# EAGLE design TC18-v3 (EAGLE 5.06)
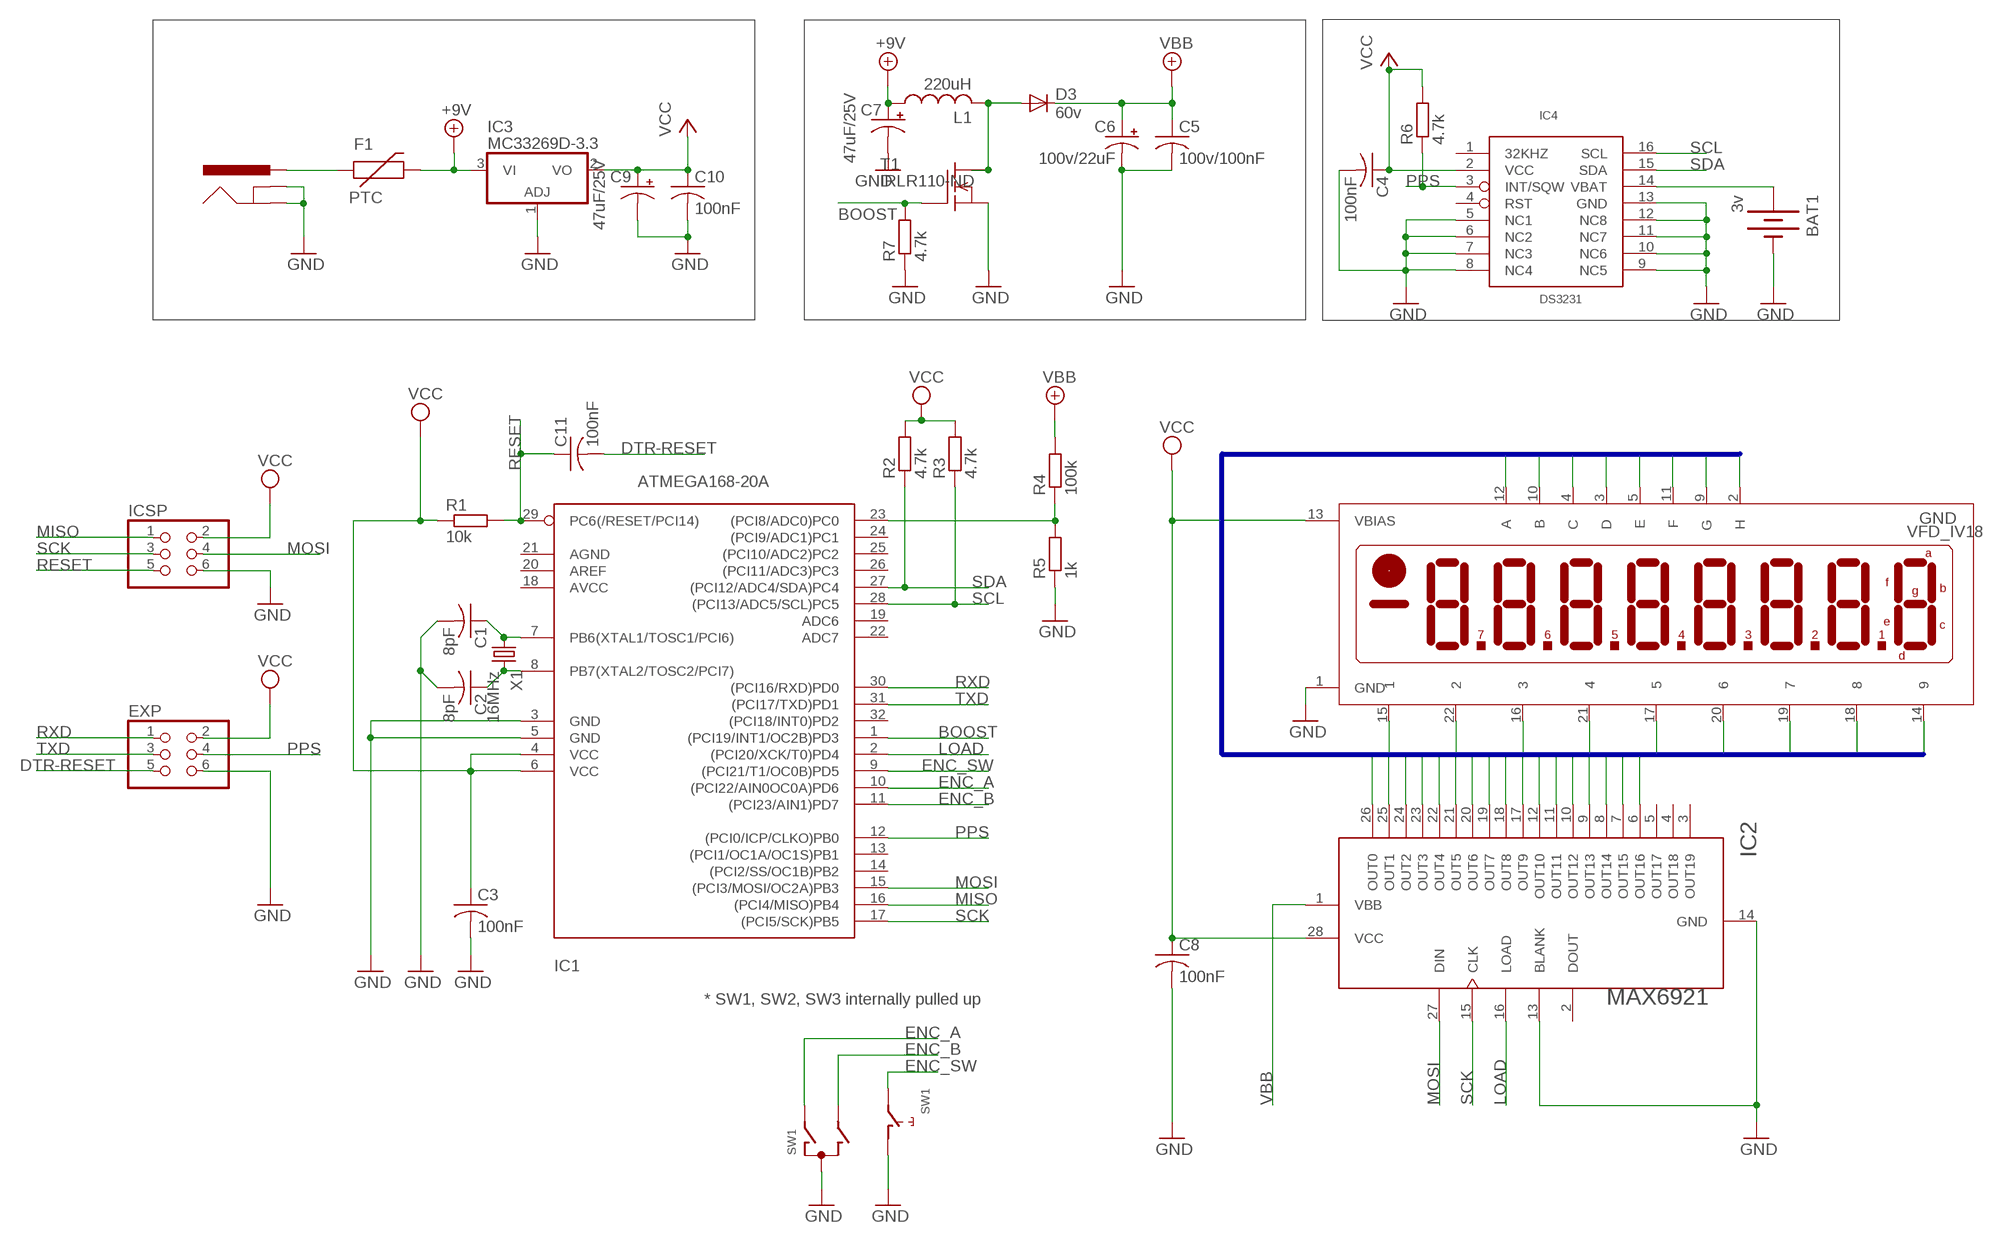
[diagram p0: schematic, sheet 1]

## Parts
BAT1  3v  BATTERY12MM  [BATTCON_12MM]
C1  8pF  C-USC0805  [C0805]
C2  8pF  C-USC0805  [C0805]
C3  100nF  C-USC0805  [C0805]
C4  100nF  C-USC0805  [C0805]
C5  100v/100nF  C-USC0805  [C0805]
C6  100v/22uF  CPOL-USE  [PANASONIC_E]
C7  47uF/25V  CPOL-USD  [PANASONIC_D]
C8  100nF  C-USC0805  [C0805]
C9  47uF/25V  CPOL-USD  [PANASONIC_D]
C10  100nF  C-USC0805  [C0805]
C11  100nF  C-USC0805  [C0805]
D3  60v  DIODE-DO214AA  [DO214AA]
EXP  PINHD-2X3  [2X03]
F1  PTC  [PTC-1210L]
GND  VFD_IV18  [VFD_IV18]
IC1  ATMEGA168-20A  [TQFP32-08]
IC2  MAX6921  MAX6921SOIC28W  [SO-28W]
IC3  MC33269D-3.3  [DPACK]
IC4  DS3231  [SO16W]
ICSP  PINHD-2X3  [2X03]
J1  POWER_JACKSMD  [POWER_JACK_SMD]
L1  220uH  INDUCTOR  [MURATA_4600]
R1  10k  R-EU_R0805  [R0805]
R2  4.7k  R-EU_R0805  [R0805]
R3  4.7k  R-EU_R0805  [R0805]
R4  100k  R-EU_R0805  [R0805]
R5  1k  R-EU_R0805  [R0805]
R6  4.7k  R-EU_R0805  [R0805]
R7  4.7k  R-EU_R0805  [R0805]
SW1  ROT_ENCODER_SW  [ACZ11BRXE-ROTARY-ENCODER-W-SWITCH]
T1  IRLR110-ND  [TO252]
X1  16MHz  CRYSTAL  [CRYSTAL-SMD-5X3.2-2PIN]

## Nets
1: GND.15 IC2.26(OUT0)
2: GND.22 IC2.25(OUT1)
3: GND.16 IC2.24(OUT2)
4: GND.21 IC2.23(OUT3)
5: GND.17 IC2.22(OUT4)
6: GND.20 IC2.21(OUT5)
7: GND.19 IC2.20(OUT6)
8: GND.18 IC2.19(OUT7)
9: GND.14 IC2.18(OUT8)
+9V [Power]: C7.+ F1.P$2 IC3.3(VI) L1.P$1
A: GND.12(A) IC2.17(OUT9)
B: GND.10(B) IC2.12(OUT10)
BOOST: IC1.1((PCI19/INT1/OC2B)PD3) R7.2 T1.1(G)
C: GND.4(C) IC2.11(OUT11)
D: GND.3(D) IC2.10(OUT12)
DTR-RESET: C11.2 EXP.5
E: GND.5(E) IC2.9(OUT13)
ENC_A: IC1.10((PCI22/AIN0OC0A)PD6) SW1.A
ENC_B: IC1.11((PCI23/AIN1)PD7) SW1.B
ENC_SW: IC1.9((PCI21/T1/OC0B)PD5) SW1.S2
F: GND.11(F) IC2.8(OUT14)
G: GND.9(G) IC2.7(OUT15)
GND [Power]: BAT1.GND(-) C1.2 C2.2 C3.2 C4.2 C5.2 C6.- C7.- C8.2 C9.- C10.2 EXP.6 GND.1(GND) IC1.3(GND) IC1.5(GND) IC2.13(BLANK) IC2.14(GND) IC3.1(ADJ) IC4.5(NC1) IC4.6(NC2) IC4.7(NC3) IC4.8(NC4) IC4.9(NC5) IC4.10(NC6) IC4.11(NC7) IC4.12(NC8) IC4.13(GND) ICSP.6 J1.GND(GNDBREAK) J1.P$4(GND) R5.1 R7.1 SW1.C SW1.S1 T1.2(S)
H: GND.2(H) IC2.6(OUT16)
LOAD: IC1.2((PCI20/XCK/T0)PD4) IC2.16(LOAD)
MISO: IC1.16((PCI4/MISO)PB4) ICSP.1
MOSI: IC1.15((PCI3/MOSI/OC2A)PB3) IC2.27(DIN) ICSP.4
N$1 [Power]: D3.A L1.P$2 T1.3(D)
N$2: C1.1 IC1.7(PB6(XTAL1/TOSC1/PCI6)) X1.P$1
N$3: C2.1 IC1.8(PB7(XTAL2/TOSC2/PCI7)) X1.P$2
N$4: IC1.23((PCI8/ADC0)PC0) R4.1 R5.2
N$5: BAT1.PWR@1(+) IC4.14(VBAT)
N$6 [Power]: F1.P$1 J1.VIN0(PWR)
PPS: EXP.4 IC1.12((PCI0/ICP/CLKO)PB0) IC4.3(INT/SQW) R6.1
RESET: C11.1 IC1.29(PC6(/RESET/PCI14)) ICSP.5 R1.2
RXD: EXP.1 IC1.30((PCI16/RXD)PD0)
SCK: IC1.17((PCI5/SCK)PB5) IC2.15(CLK) ICSP.3
SCL: IC1.28((PCI13/ADC5/SCL)PC5) IC4.16(SCL) R3.1
SDA: IC1.27((PCI12/ADC4/SDA)PC4) IC4.15(SDA) R2.1
TXD: EXP.3 IC1.31((PCI17/TXD)PD1)
VBB [Power]: C5.1 C6.+ D3.C IC2.1(VBB) R4.2
VCC [Power]: C3.1 C4.1 C8.1 C9.+ C10.1 EXP.2 GND.13(VBIAS) IC1.4(VCC) IC1.6(VCC) IC2.28(VCC) IC3.2(VO) IC4.2(VCC) ICSP.2 R1.1 R2.2 R3.2 R6.2
Unconnected: IC1.13((PCI1/OC1A/OC1S)PB1) IC1.14((PCI2/SS/OC1B)PB2) IC1.18(AVCC) IC1.19(ADC6) IC1.20(AREF) IC1.21(AGND) IC1.22(ADC7) IC1.24((PCI9/ADC1)PC1) IC1.25((PCI10/ADC2)PC2) IC1.26((PCI11/ADC3)PC3) IC1.32((PCI18/INT0)PD2) IC2.2(DOUT) IC2.3(OUT19) IC2.4(OUT18) IC2.5(OUT17) IC4.1(32KHZ) IC4.4(RST) SW1.P$1(G) SW1.P$2(G)

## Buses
VFD:VBIAS,GND,1,2,3,4,5,6,7,8,9,A,B,C,D,E,F,G,H

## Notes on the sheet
- * SW1, SW2, SW3 internally pulled up

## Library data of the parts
BAT1 = JVN:BATTERY: Battery Holders
C1-C5 C8 C10 C11 = rcl:C-US: CAPACITOR, American symbol
C6 C7 C9 = rcl:CPOL-US: POLARIZED CAPACITOR, American symbol
D3 = diode:DIODE-: DIODE
EXP ICSP = JVN:PINHD-2X3: PIN HEADER
F1 = JVN:PTC: Resettable Fuse PTC
GND = JVN:VFD_IV18: LCD DISPLAY 8-character 7 segment
IC1 = avr:ATMEGA168: MICROCONTROLLER 16 kBytes FLASH 1 kBytes SRAM 512 Bytes EEPROM USART 8-channel 10 bit ADC
IC2 = JVN:MAX6921
IC3 = linear:MC33269?*: Adjustable Output Low Dropout Voltage Regulator 800 mA Source: http://www.onsemi.com/pub/Collateral/MC33269-D.PDF
IC4 = JVN:DS3231
J1 = SparkFun:POWER_JACK: Power Jack This is the standard 5.5mm barrel jack for power. The PTH is the most common, proven, reliable, footprint. All others are experimental. The Slot footprint only works if the mill layer is transmitted to the PCB fab house so be warned. Spark Fun Electronics SKU : PRT-00119. Mating wall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
L1 = JVN:INDUCTOR: INDUCTOR, American symbol
R1-R7 = rcl:R-EU_: RESISTOR, European symbol
SW1 = JVN:ROT_ENCODER_SW: ALPS rotary Encoder EC12E series with switch
T1 = JVN:IRLR110-ND
X1 = JVN:CRYSTAL: Crystals

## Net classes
1 Power: width 0.305 mm

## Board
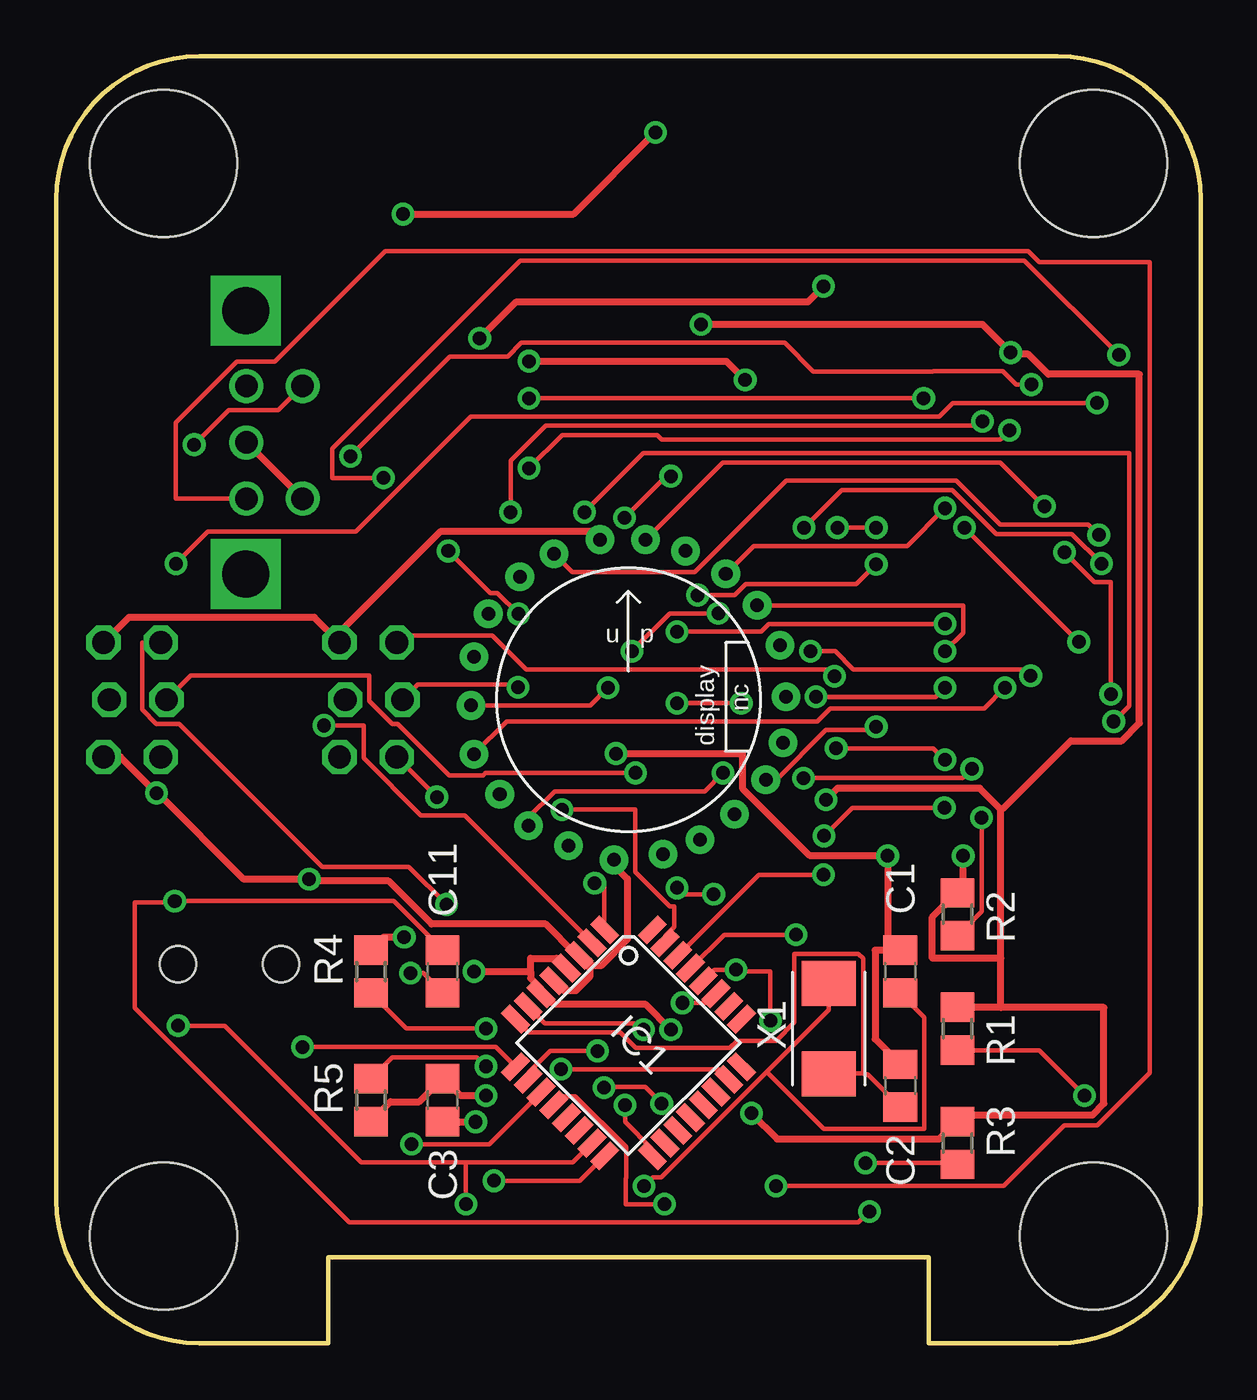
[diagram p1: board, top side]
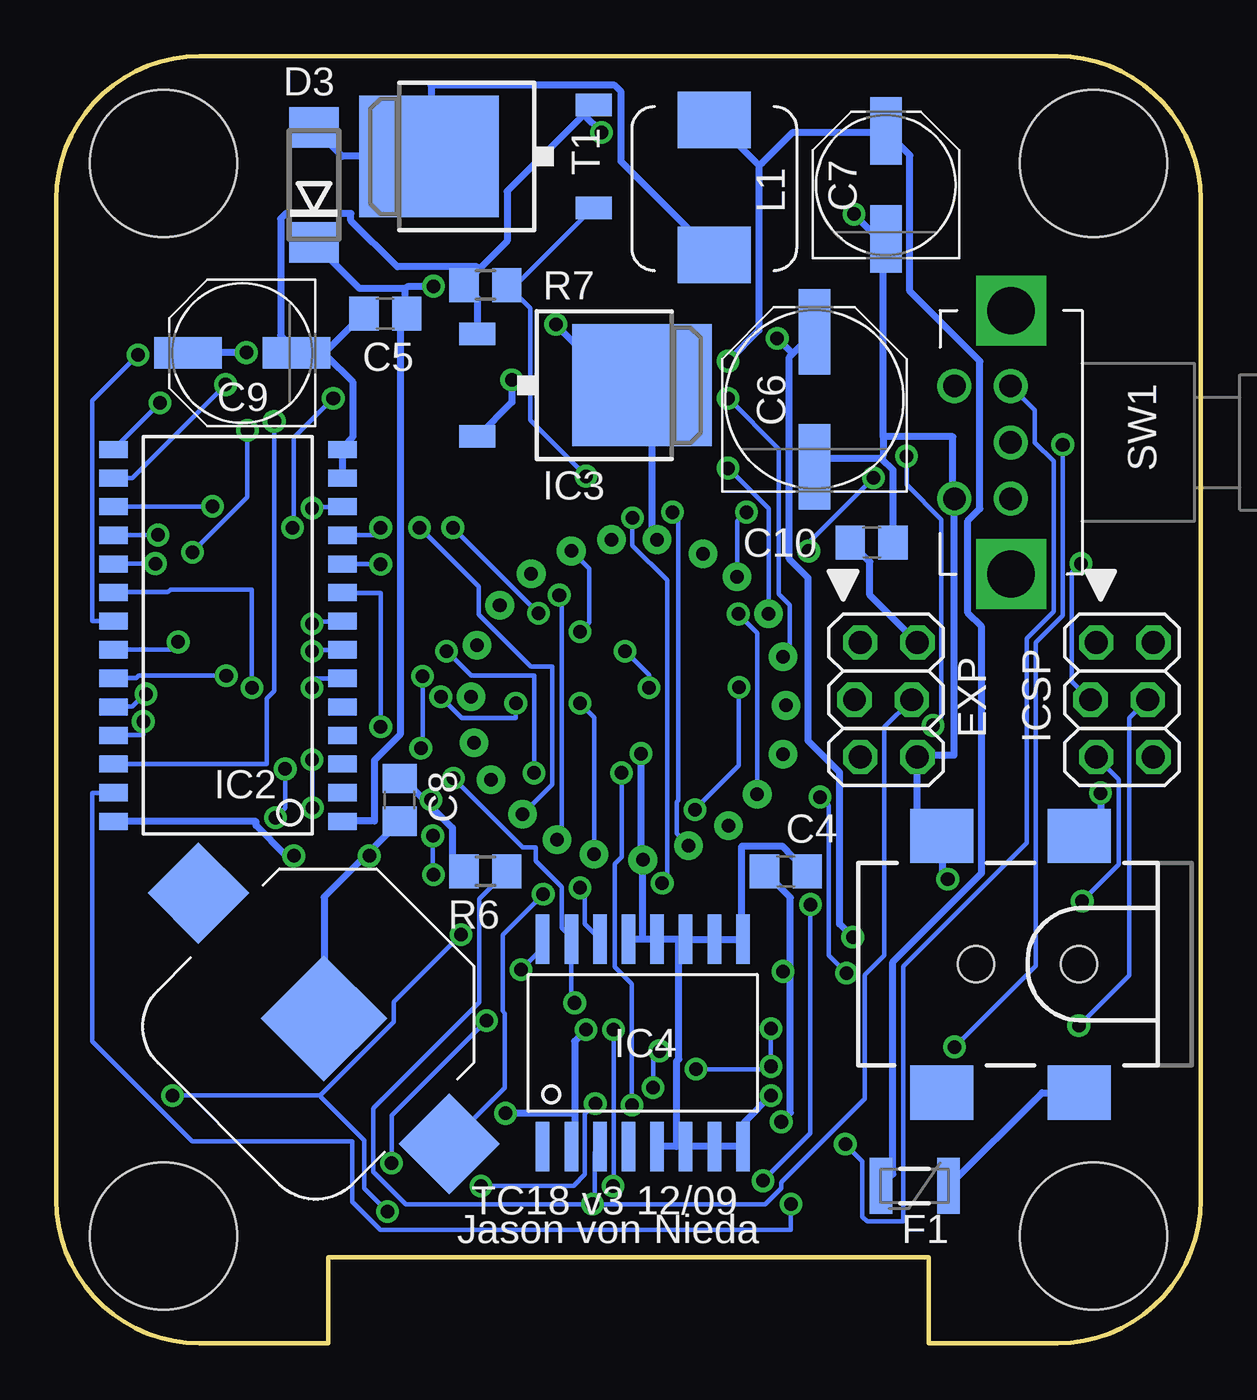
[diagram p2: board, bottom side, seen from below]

Size 50.8 x 57.15 mm. Coordinates in mm from the lower left corner, seen from the top.
Outline: 0,50.8 arc-90 6.35,57.15 44.45,57.15 arc-90 50.8,50.8 50.8,6.35 arc-90 44.45,0 38.73,0 38.73,3.81 12.06,3.81 12.06,0 6.35,0 arc-90 0,6.35 0,50.8
Copper layers (1*16): Top 0.035mm / dielectric 1.5mm / Bottom 0.035mm
Design rules "GoldPhoenix": minimum track width 8mil, minimum drill 0.6mm, track to track 8mil, track to pad 8mil, pad to pad 8mil, via to via 8mil, smd to smd 8mil, copper to edge 40mil, drill to drill 10mil, minimum pad ring 10mil, minimum via ring 8mil, stop-mask expansion 4mil, vias tented up to drill 24mil, thermal gap 10mil
Holes 6.53 mm at 4.76,4.76 46.04,4.76 4.76,52.39 46.04,52.39

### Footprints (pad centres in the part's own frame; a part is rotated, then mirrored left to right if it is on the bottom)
BATTCON_12MM = smd 3.962 x 3.962: GND 0,0 | smd 3.175 x 3.175: PWR@1 -7.874,0; PWR@2 7.874,0
C0805 = smd 1.3 x 1.5: 1 -0.95,0; 2 0.95,0
PANASONIC_E = smd 3.8 x 1.4: + 3,0; - -3,0
PANASONIC_D = smd 3 x 1.4: + 2.4,0; - -2.4,0
DO214AA = smd 1.8 x 2.2: A 2.55,0; C -2.55,0
2X03 = drill 1.016 octagon: 1 -2.54,-1.143; 2 -2.54,1.397; 3 0,-1.397; 4 0,1.143; 5 2.54,-1.143; 6 2.54,1.397
PTC-1210L = smd 1 x 2.5: P$1 -1.5,0; P$2 1.5,0
VFD_IV18 = drill 0.6 pad 1.27 round: 1 -0.635,-7.112; 2 1.524,-6.858; 3 3.175,-6.223; 4 4.699,-5.08; 5 6.096,-3.556; 6 6.858,-1.905; 7 6.985,0.127; 8 6.731,2.413; 9 5.715,4.191; 10 4.318,5.588; 11 2.54,6.604; 12 0.762,7.112; 13 -1.27,7.112; 14 -3.302,6.477; 15 -4.826,5.461; 16 -6.223,3.81; 17 -6.858,1.905; 18 -6.985,-0.254; 19 -6.858,-2.413; 20 -5.715,-4.191; 21 -4.445,-5.588; 22 -2.667,-6.477
TQFP32-08 = smd 1.27 x 0.559: 1 -4.293,2.8; 2 -4.293,2; 3 -4.293,1.2; 4 -4.293,0.4; 5 -4.293,-0.4; 6 -4.293,-1.2; 7 -4.293,-2; 8 -4.293,-2.8; 17 4.293,-2.8; 18 4.293,-2; 19 4.293,-1.2; 20 4.293,-0.4; 21 4.293,0.4; 22 4.293,1.2; 23 4.293,2; 24 4.293,2.8 | smd 0.559 x 1.27: 9 -2.8,-4.293; 10 -2,-4.293; 11 -1.2,-4.293; 12 -0.4,-4.293; 13 0.4,-4.293; 14 1.2,-4.293; 15 2,-4.293; 16 2.8,-4.293; 25 2.8,4.293; 26 2,4.293; 27 1.2,4.293; 28 0.4,4.293; 29 -0.4,4.293; 30 -1.2,4.293; 31 -2,4.293; 32 -2.8,4.293
SO-28W = smd 0.762 x 1.27: 1 -8.255,-5.08; 2 -6.985,-5.08; 3 -5.715,-5.08; 4 -4.445,-5.08; 5 -3.175,-5.08; 6 -1.905,-5.08; 7 -0.635,-5.08; 8 0.635,-5.08; 9 1.905,-5.08; 10 3.175,-5.08; 11 4.445,-5.08; 12 5.715,-5.08; 13 6.985,-5.08; 14 8.255,-5.08; 15 8.255,5.08; 16 6.985,5.08; 17 5.715,5.08; 18 4.445,5.08; 19 3.175,5.08; 20 1.905,5.08; 21 0.635,5.08; 22 -0.635,5.08; 23 -1.905,5.08; 24 -3.175,5.08; 25 -4.445,5.08; 26 -5.715,5.08; 27 -6.985,5.08; 28 -8.255,5.08
DPACK = smd 1 x 1.6: 1 -2.28,-4.8; 3 2.28,-4.8 | smd 5.4 x 6.2: 2 0,2.5
SO16W = smd 0.6 x 2.2: 1 -4.445,-4.6; 2 -3.175,-4.6; 3 -1.905,-4.6; 4 -0.635,-4.6; 5 0.635,-4.6; 6 1.905,-4.6; 7 3.175,-4.6; 8 4.445,-4.6; 9 4.445,4.6; 10 3.175,4.6; 11 1.905,4.6; 12 0.635,4.6; 13 -0.635,4.6; 14 -1.905,4.6; 15 -3.175,4.6; 16 -4.445,4.6
POWER_JACK_SMD = smd 2.8 x 2.4: GND 0,-5.7; P$4 6.1,-5.7; VIN0 0,5.7; VIN1 6.1,5.7 | hole 1.6: 0,0; 4.572,0
MURATA_4600 = smd 2.5 x 3.25: P$1 -3.05,0; P$2 2.95,0
R0805 = smd 1.3 x 1.5: 1 -0.95,0; 2 0.95,0
ACZ11BRXE-ROTARY-ENCODER-W-SWITCH = drill 1 round: A -2.5,0.02; B 2.5,0.02; C 0,0.02; S1 -2.5,2.52; S2 2.5,2.52 | drill 2.1 square: P$1 -5.85,0; P$2 5.85,0
TO252 = smd 1 x 1.6: 1 -2.28,-4.8; 2 2.28,-4.8 | smd 5.4 x 6.2: 3 0,2.5
CRYSTAL-SMD-5X3.2-2PIN = smd 2 x 2.4: P$1 -2,0; P$2 2,0

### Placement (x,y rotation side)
BAT1  38.92,14.42 135 bottom
C1  37.47,16.51 90 top
C2  37.47,11.43 90 top
C3  17.14,10.79 90 top
C4  18.41,20.95 0 bottom
C5  36.2,45.72 180 bottom
C6  17.14,41.91 90 bottom
C7  13.97,51.44 90 bottom
C8  35.56,24.13 270 bottom
C9  42.55,43.97 180 bottom
C10  14.61,35.56 0 bottom
C11  17.14,16.51 270 top
D3  39.37,51.44 90 bottom
EXP  13.97,28.57 270 bottom
F1  12.7,6.99 180 bottom
GND  25.4,28.57 0 top
IC1  25.4,13.34 315 top
IC2  43.18,31.43 90 bottom
IC3  27.3,42.55 270 bottom
IC4  24.77,13.34 0 bottom
ICSP  3.49,28.57 270 bottom
J1  5.4,16.83 180 bottom
L1  21.59,51.28 270 bottom
R1  40.01,13.97 270 top
R2  40.01,19.05 90 top
R3  40.01,8.89 90 top
R4  13.97,16.51 90 top
R5  13.97,10.79 90 top
R6  31.75,20.95 180 bottom
R7  31.75,46.99 0 bottom
SW1  8.41,40.01 90 bottom
T1  31.75,52.7 90 bottom
X1  34.29,13.97 270 top

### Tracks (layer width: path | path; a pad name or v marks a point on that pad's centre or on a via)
1  (via drill 0.6)
  Top 0.203: v41.12,40.95 40.92,40.74 21.72,40.74 20.17,39.19 v20.17,36.91
  Bottom 0.203: v41.12,40.95 41.12,28.96 41.45,28.63 41.45,25.73 IC2.26 | v20.17,36.91 20.57,36.5 GND.15
2  (via drill 0.6)
  Top 0.203: v46.94,27.61 47.62,28.3 47.62,39.52 26.06,39.52 v23.44,36.91
  Bottom 0.203: v46.94,27.61 46.94,27 IC2.25 | v23.44,36.91 23.19,36.65 23.19,24.11 23.27,24.03 23.27,22.63 GND.22
3  (via drill 0.6)
  Top 0.203: v46.81,28.83 46.81,33.81 46.08,33.81 v44.76,35.13 | v42.32,40.54 41.91,40.13 26.87,40.13 26.67,40.34 22.45,40.34 v20.98,38.86
  Bottom 0.203: v46.81,28.83 46.86,28.83 47.42,28.27 IC2.24 | v44.76,35.13 42.32,37.57 v42.32,40.54 | v20.98,38.86 19.18,37.06 GND.16
4  (via drill 0.6)
  Top 0.203: v43.26,29.64 42.98,29.92 35.38,29.92 34.57,30.73 v33.48,30.73 | v29.59,25.32 28.78,24.51 22.12,24.51 20.95,23.34 GND.21
  Bottom 0.203: v43.26,29.64 47.14,29.64 47.24,29.54 IC2.23 | v33.48,30.73 32.38,29.64 29.59,29.64 v29.59,25.32
5  (via drill 0.6)
  Top 0.203: v40.31,36.22 v45.39,31.14 | v20.98,41.96 v38.51,41.96
  Bottom 0.203: v45.39,31.14 45.39,30.81 IC2.22 | v40.31,36.22 40.26,36.27 40.26,40.21 v38.51,41.96 | v20.98,41.96 18.72,39.7 18.72,33.27 18.24,32.79 18.24,30.79 GND.17
6  (via drill 0.6)
  Top 0.203: v47.17,43.89 42.98,48.08 20.6,48.08 12.24,39.73 12.24,38.43 v14.53,38.43 | v17.4,35.18 19.25,33.33 19.58,33.33 v20.52,32.38
  Bottom 0.203: v47.17,43.89 49.2,41.86 49.2,32.08 IC2.21 | v14.53,38.43 17.4,35.56 v17.4,35.18 | v20.52,32.38 19.68,31.55 GND.20
7  (via drill 0.6)
  Top 0.203: v42.11,29.11 41.2,28.19 34.37,28.19 33.78,27.61 19.99,27.61 GND.19
  Bottom 0.203: v42.11,29.11 42.11,33.48 45.72,33.48 45.85,33.35 IC2.20
8  (via drill 0.6)
  Top 0.203: v46.41,34.62 45.09,35.94 41.73,35.94 39.78,37.9 34.87,37.9 v33.2,36.22 | v29.39,32.41 27.23,32.41 v25.55,30.73 | v24.49,29.11 23.7,28.32 GND.18
  Bottom 0.203: v46.41,34.62 IC2.19 | v29.39,32.41 v33.2,36.22 | v25.55,30.73 24.49,29.67 v24.49,29.11
9  (via drill 0.6)
  Top 0.203: v46.28,35.89 45.82,36.35 41.91,36.35 39.95,38.3 32.41,38.3 28.35,34.24 22.91,34.24 GND.14
  Bottom 0.203: v46.28,35.89 IC2.18
+9V  (via drill 0.6)
  Top 0.305: v30.58,42.77 29.74,43.61 v20.98,43.61
  Bottom 0.305: v30.58,42.77 30.58,41.78 32.08,40.28 IC3.3 | v20.98,43.61 19.61,44.98 19.61,52.32 | 19.61,52.32 21.59,54.3 L1.P$1 | F1.P$2 13.66,7.52 13.66,16.94 9.73,20.88 9.73,31.83 10.34,32.44 10.34,36.52 9.8,37.06 9.8,43.61 12.9,46.71 12.9,52.76 13.97,53.82 C7.+ 14.1,53.75 18.14,53.75 19.48,52.4 19.61,52.32
A  (via drill 0.6)
  Top 0.203: v43.87,37.16 41.91,39.12 29.59,39.12 GND.12
  Bottom 0.203: v43.87,37.16 IC2.17
B  (via drill 0.6)
  Top 0.203: v39.45,37.08 37.77,35.41 30.96,35.41 GND.10
  Bottom 0.203: v39.45,37.08 39.45,37.13 38.1,37.13 IC2.12
BOOST  (via drill 0.6)
  Top 0.203: v23.9,20.42 24.33,20.42 24.33,18.36 IC1.1 | v25.22,36.65 27.08,38.51 v27.28,38.51
  Bottom 0.203: v23.9,20.42 23.67,20.65 23.67,33.88 25.22,35.43 v25.22,36.65 | v27.28,38.51 29.77,41 29.77,45.97 30.79,46.99 R7.2 30.53,46.86 26.98,50.42 T1.1
C  (via drill 0.6)
  Top 0.203: v34.67,36.22 v36.4,36.22
  Bottom 0.203: v36.4,36.22 36.4,35.89 IC2.11 | v34.67,36.22 32.05,33.6 32.05,32.36 29.74,30.05 28.78,30.05 28.78,24.82 GND.4
D  (via drill 0.6)
  Top 0.203: v36.4,34.59 35.51,33.71 30.61,33.71 30.12,33.22 v28.47,33.22
  Bottom 0.203: v36.4,34.59 38.1,34.59 IC2.10 | v28.47,33.22 28.37,33.12 28.37,22.55 GND.3
DTR-RESET  (via drill 0.6)
  Top 0.203: v15.72,16.43 16.28,16.43 C11.2 | v16.89,24.26 EXP.5
  Bottom 0.203: v15.72,16.43 16.51,17.22 16.51,23.88 v16.89,24.26
E  (via drill 0.6)
  Top 0.203: v36.4,27.38 36.25,27.23 34.16,27.23 31.95,25.02 GND.5
  Bottom 0.203: v36.4,27.38 36.4,33.33 38.1,33.33 IC2.9
ENC_A  (via drill 0.6)
  Top 0.203: v24.03,12.98 21.92,12.98 20.95,12.01 20.95,11.73 IC1.10 | v24.31,11.35 24.33,11.38 26.14,11.38 v26.87,10.64 | v31.95,6.99 42.06,6.99 44.76,9.68 46.2,9.68 48.54,12.01 48.54,48.01 43.64,48.01 43.16,48.49 14.61,48.49 9.7,43.59 8,43.59 5.31,40.89 5.31,37.52 SW1.A
  Bottom 0.203: v24.03,12.98 24.31,12.7 v24.31,11.35 | v26.87,10.64 27.33,10.19 27.33,7.49 27.84,6.99 v31.95,6.99
ENC_B  (via drill 0.6)
  Top 0.203: v15.77,8.84 19.23,8.84 21.51,11.12 IC1.11
  Bottom 0.203: v15.77,8.84 15.01,8.08 15.01,5.61 14.81,5.41 13.21,5.41 13.21,16.74 7.72,22.23 7.72,31.29 6.53,32.49 6.53,39.17 7.37,40.01 7.37,41.43 8.43,42.49 SW1.B
ENC_SW  (via drill 0.6)
  Top 0.203: v10.92,13.16 19.51,13.16 20.37,12.29 IC1.9 | v6.12,39.9 7.64,41.43 9.86,41.43 10.92,42.49 SW1.S2
  Bottom 0.203: v10.92,13.16 7.32,16.76 7.32,31.11 6.12,32.31 v6.12,39.9
F  (via drill 0.6)
  Top 0.203: v39.45,31.95 39.42,31.93 31.62,31.93 31.29,31.6 v27.56,31.6
  Bottom 0.203: v39.45,31.95 39.45,32.05 38.1,32.05 IC2.8 | v27.56,31.6 27.15,32 27.15,34.39 GND.11
G  (via drill 0.6)
  Top 0.203: v39.45,30.73 40.26,31.55 40.26,32.77 GND.9
  Bottom 0.203: v39.45,30.73 39.45,30.79 38.1,30.79 IC2.7
GND  (via drill 0.6)
  Top 0.305: C2.2 37.47,12.39 36.35,13.51 36.35,17.45 C1.2 36.91,17.58 v36.91,21.64 36.78,21.67 33.43,21.67 30.45,24.64 30.45,26.19 v24.84,26.19 | R5.1 14.83,10.72 16.1,10.72 17.12,11.73 C3.2 17.27,11.66 17.93,11 v19.07,11 | 23.67,16.76 23.67,16.99 23.42,16.99 23.22,17.2 IC1.3 23.06,17.27 21.72,18.62 16.66,18.62 14.76,20.52 11.35,20.52 v11.23,20.6 8.33,20.6 4.57,24.36 v4.45,24.43 2.85,26.04 ICSP.6 | 23.67,16.76 23.67,16.26 23.06,15.65 22.53,15.65 22.1,16.08 IC1.5 | GND.1 24.77,21.21 25.35,20.62 25.35,17.93 24.18,16.76 23.67,16.76 | SW1.C 8.46,40.01 10.95,37.52 SW1.S1 | v26.59,53.77 22.96,50.14 v15.39,50.14
  Bottom 0.305: 36.99,21.73 38.91,19.81 BAT1.GND | 36.99,21.73 35.56,23.16 C8.2 | v36.91,21.64 36.99,21.73 | 23.27,8.74 22.99,8.74 IC4.6 21.72,8.74 IC4.7 IC4.8 20.24,8.87 20.24,9.83 v19.07,11 | 23.27,8.74 IC4.5 | C4.2 17.48,20.95 18.34,21.82 18.34,21.84 18.57,22.07 20.37,22.07 20.37,18.01 20.32,17.96 IC4.9 20.5,17.93 IC4.10 21.72,17.93 IC4.11 22.99,17.93 23.16,17.93 | 23.16,17.93 IC4.12 24.26,17.93 24.77,17.93 | 24.77,17.93 IC4.13 | 24.77,17.93 GND.1 24.84,21.59 v24.84,26.19 | 23.27,8.74 23.27,12.52 23.16,12.62 23.16,17.93 | IC2.13 IC2.14 38.05,39.83 37.64,40.23 37.64,42.7 38.81,43.87 C9.- | C5.2 38.89,43.99 40.13,43.99 C9.- | IC3.1 32.11,46.41 R7.1 32.61,47.12 32.03,47.7 | 27.38,54.56 30.79,51.16 30.79,48.95 32.03,47.7 | 27.38,54.56 26.98,54.97 T1.2 | C9.- 40.21,44.12 40.84,44.76 40.84,49.94 40.62,50.16 37.72,50.16 37.72,49.86 35.66,47.8 32.13,47.8 32.03,47.7 | 14.17,39.29 13.66,38.79 C10.2 | 14.17,39.29 17.14,39.29 C6.- | 14.1,40.26 14.1,39.42 14.17,39.29 | 14.1,40.26 14.1,48.9 13.97,49.02 C7.- 14.22,48.97 v15.39,50.14 | v4.45,24.43 4.45,23.47 5.38,22.53 J1.GND | v11.23,20.6 11.46,20.83 11.46,22.38 J1.P$4 12.57,23.6 EXP.6 12.45,26.11 10.95,26.11 10.95,37.49 SW1.S1 11,37.64 11,40.26 14.1,40.26 | v26.59,53.77 27.38,54.56
H  (via drill 0.6)
  Top 0.203: v39.45,29.11 39.04,28.7 v33.73,28.7 | v27.56,28.42 v30.4,28.42
  Bottom 0.203: v39.45,29.11 39.45,29.52 38.1,29.52 IC2.6 | v33.73,28.7 32.79,27.76 30.4,27.76 v30.4,28.42 | v27.56,28.42 26.92,27.79 GND.2
LOAD  (via drill 0.6)
  Top 0.203: v11.89,27.43 13.64,27.43 13.64,25.98 16.18,23.44 18.14,23.44 23.77,17.8 IC1.2 | v13.06,39.4 17.48,43.81 20.04,43.81 20.65,44.42 32.33,44.42 33.6,43.16 38.91,43.16 38.94,43.18 42.01,43.18 42.62,42.57 v43.28,42.57
  Bottom 0.203: v11.89,27.43 11.51,27.81 11.51,36.58 13.06,38.12 v13.06,39.4 | v43.28,42.57 47.42,38.43 IC2.16
MISO  (via drill 0.6)
  Top 0.203: v19.43,7.21 23.24,7.21 24.33,8.31 IC1.16 | v17.32,19.48 15.65,21.16 11.81,21.16 5.46,27.51 4.45,27.51 3.81,28.14 3.81,31.11 ICSP.1
  Bottom 0.203: v19.43,7.21 17.32,9.32 v17.32,19.48
MOSI  (via drill 0.6)
  Top 0.203: 18.19,8.03 13.54,8.03 7.47,14.1 v5.41,14.1 | 18.19,8.03 22.94,8.03 23.77,8.87 IC1.15 | 18.19,8.03 v18.19,6.17
  Bottom 0.203: v5.41,14.1 3.17,16.33 3.17,27.76 2.36,28.57 ICSP.4 | v18.19,6.17 18.19,5.03 36.42,5.03 37.67,6.27 37.67,8.97 44.76,8.97 49.2,13.41 49.2,24.43 48.26,24.43 IC2.27
N$1
  Bottom 0.305: D3.A 38.1,52.7 T1.3 34.16,52.83 34.16,55.85 26.01,55.85 25.73,55.58 25.73,52.48 L1.P$2
N$2  (via drill 0.6)
  Top 0.203: v26.06,13.92 25.78,14.2 21.69,14.2 20.95,14.94 IC1.7 | v26.09,6.99 26.47,7.37 26.85,7.37 31.53,12.05 | 31.53,12.05 34.29,14.81 X1.P$1 | C1.1 37.47,15.54 38.53,14.48 38.53,9.53 34.06,9.53 31.53,12.05
  Bottom 0.203: v26.06,13.92 26.06,7.01 v26.09,6.99
N$3
  Top 0.203: 35.81,11.99 35.81,17.09 35.61,17.3 32.77,17.3 32.77,14.25 31.95,13.44 30.23,13.44 29.9,13.11 25.73,13.11 25.04,13.79 20.98,13.79 20.4,14.38 IC1.8 | 35.81,11.99 34.29,11.99 X1.P$2 | C2.1 36.02,11.94 35.89,11.94 35.81,11.99
N$4  (via drill 0.6)
  Top 0.203: v22.4,12.17 29.41,12.17 29.84,11.73 IC1.23 | v19.07,12.29 18.67,12.7 14.91,12.7 13.97,11.76 R5.2 | v19.07,13.97 15.54,13.97 13.97,15.54 R4.1
  Bottom 0.203: v22.4,12.17 19.07,12.17 v19.07,12.29 v19.07,13.97
N$5  (via drill 0.6)
  Top 0.203: v27.56,20.22 27.84,19.94 v29.18,19.94
  Bottom 0.203: v27.56,20.22 27.33,19.99 27.33,18.62 26.67,17.96 IC4.14 | v29.18,19.94 30.99,18.14 30.99,14.76 30.89,14.66 30.89,11.33 33.35,8.87 BAT1.PWR@1
N$6
  Bottom 0.305: F1.P$1 11.18,6.99 7.04,11.12 J1.VIN0
PPS  (via drill 0.6)
  Top 0.203: v27,6.17 25.27,6.17 25.27,7.32 25.3,7.34 25.3,8.71 23.04,10.97 22.48,10.97 22.1,10.59 IC1.12
  Bottom 0.203: v27,6.17 26.9,6.27 26.9,8.48 26.67,8.71 IC4.3 | R6.1 32.03,19.74 32.03,15.14 36.73,10.44 36.73,7.62 35.28,6.17 v27,6.17 | EXP.4 14.05,27.36 14.05,17.22 14.91,16.36 14.91,10.85 18.62,7.14 18.62,6.88 19.33,6.17 26.82,6.17 26.82,6.22 v27,6.17
RESET  (via drill 0.6)
  Top 0.203: v32.84,18.14 29.64,18.14 28.17,16.66 IC1.29 | v45.64,11 43.64,13.01 40.01,13.01 R1.2 | C11.1 17.14,17.48 14.99,19.63 v5.26,19.63 5.18,19.58 3.48,19.58 3.48,14.88 13.01,5.36 35.61,5.36 v36.09,5.84
  Bottom 0.203: v32.84,18.14 35.81,15.16 35.81,14.28 39.09,11 | 39.09,11 v45.64,11 | v5.26,19.63 3.63,21.26 3.63,25.04 4.62,26.04 ICSP.5 | v36.09,5.84 37.13,6.88 37.13,9.02 39.04,10.92 39.09,11
RXD  (via drill 0.6)
  Top 0.203: v34.06,20.8 31.19,20.8 27.61,17.22 IC1.30 | v34.09,22.53 35.33,23.77 v39.42,23.77 | v39.45,25.91 38.94,26.42 v34.62,26.42 | v34.54,29.62 34.24,29.92 20.85,29.92 19.36,31.42 15.42,31.42 EXP.1
  Bottom 0.203: v34.06,20.8 34.09,20.83 v34.09,22.53 | v39.42,23.77 39.45,23.8 v39.45,25.91 | v34.62,26.42 34.54,26.49 v34.54,29.62
SCK  (via drill 0.6)
  Top 0.203: v25.25,10.57 25.25,9.83 26.44,8.64 26.44,8.33 IC1.17 | v25.7,25.32 19.05,25.32 18.95,25.22 17.45,25.22 15.16,27.51 14.91,27.51 13.89,28.52 13.89,29.64 5.97,29.64 4.9,28.57 ICSP.3 | v46.2,41.76 39.8,41.76 39.19,41.15 18.39,41.15 13.28,36.04 6.73,36.04 v5.31,34.62
  Bottom 0.203: v25.25,10.57 25.25,15.95 26.01,16.71 26.01,21.29 25.7,21.59 v25.7,25.32 | v46.2,41.76 IC2.15 | v5.31,34.62 5.71,34.21 5.71,29.39 4.9,28.57 ICSP.3
SCL  (via drill 0.6)
  Top 0.203: IC1.28 28.73,16.1 29.21,16.59 v30.18,16.59 30.23,16.51 31.7,16.51 v31.7,14.33 | v35.92,8 39.95,8 R3.1
  Bottom 0.203: v30.18,16.59 29.21,17.55 IC4.16 | v35.92,8 35.92,10.11 v31.7,14.33
SDA  (via drill 0.6)
  Top 0.203: v27.79,15.11 28.85,15.11 29.26,15.52 IC1.27 | v41.07,23.34 41.07,19.18 R2.1 | v40.64,25.5 40.23,25.09 v33.17,25.09
  Bottom 0.203: v27.79,15.11 27.94,15.27 IC4.15 27.96,18.03 28.37,18.44 28.37,20.27 29.52,21.41 29.52,22.02 30.1,22.02 v33.17,25.09 | v41.07,23.34 40.64,23.77 v40.64,25.5
TXD  (via drill 0.6)
  Top 0.203: v22.45,23.7 25.7,23.7 25.7,20.93 27.23,19.41 27.43,19.41 27.43,18.49 27.03,18.09 27.03,17.8 IC1.31 | v20.5,29.13 20.37,29.26 16.05,29.26 EXP.3
  Bottom 0.203: v22.45,23.7 20.5,25.65 v20.5,29.13
VBB  (via drill 0.6)
  Top 0.305: v15.44,18.03 14.53,18.03 13.97,17.48 R4.2 | v34.06,46.94 33.38,46.25 20.42,46.25 v18.8,44.63
  Bottom 0.305: IC2.1 36.68,23.19 36.68,25.88 35.53,27.03 35.53,45.44 35.26,45.72 C5.1 35.33,45.85 35.33,46.84 | 35.33,46.84 37.34,46.84 39.37,48.87 D3.C | v15.44,18.03 16.03,18.62 16.03,25.35 17.42,26.75 17.42,33.98 18.26,34.82 18.26,43.79 18.11,43.94 | 18.11,43.94 C6.+ | v34.06,46.94 34.06,46.91 35.2,46.91 35.33,46.84 | 18.11,43.94 v18.8,44.63
VCC  (via drill 0.6)
  Top 0.305: 21.06,16.51 21.06,17.09 22.2,17.09 22.63,16.66 IC1.4 | 21.06,16.51 21.06,16.2 21.51,15.75 21.51,15.54 IC1.6 21.67,15.47 22.07,15.06 26.14,15.06 v27.28,13.92 | v18.62,9.83 17.14,9.83 C3.1 | v18.54,16.51 21.06,16.51 | v40.26,21.64 40.26,20.02 40.01,20.02 R2.2 39.88,19.91 38.89,18.92 38.89,17.09 41.94,17.09 | 41.94,14.91 R1.1 | 41.94,14.91 46.51,14.91 46.51,10.64 46,10.13 40.28,10.13 40.01,9.86 R3.2 39.88,9.75 39.19,9.07 32,9.07 v30.86,10.21 | v34.16,24.13 34.67,24.64 41,24.64 41.94,23.7 | 41.94,17.09 41.94,23.7 | 41.94,14.91 41.94,17.09 | ICSP.2 3.23,32.23 11.46,32.23 EXP.2 12.45,31.45 17.04,36.04 23.77,36.04 GND.13 | v28.63,45.24 41.12,45.24 v42.37,43.99 42.49,43.92 43.16,43.92 44.04,43.03 48.08,43.03 48.08,27.53 47.3,26.75 45.03,26.75 42.06,23.77 41.94,23.7
  Bottom 0.305: v18.62,9.83 18.21,10.24 18.21,16.51 | 18.21,16.51 18.21,19.79 19.36,20.93 C4.1 | 18.21,16.51 v18.54,16.51 | 27.79,10.21 27.79,13.41 v27.28,13.92 | 27.79,10.21 27.79,8.89 IC4.2 | v40.26,21.64 40.59,21.64 41.94,22.99 41.94,23.16 48.26,23.16 IC2.28 | 34.31,23.98 35.41,25.07 C8.1 | 34.31,23.98 33.22,22.89 33.22,21.46 32.72,20.95 R6.2 | v34.16,24.13 34.31,23.98 | 27.79,10.21 v30.86,10.21 | EXP.2 14.68,33.22 14.68,34.7 C10.1 | GND.13 24.36,35.92 24.36,42.11 IC3.2 24.94,42.62 26.01,42.62 v28.63,45.24 | v42.37,43.99 44.93,43.99 C9.+

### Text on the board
bPlace: TC18 v3 12/09 | Jason von Nieda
